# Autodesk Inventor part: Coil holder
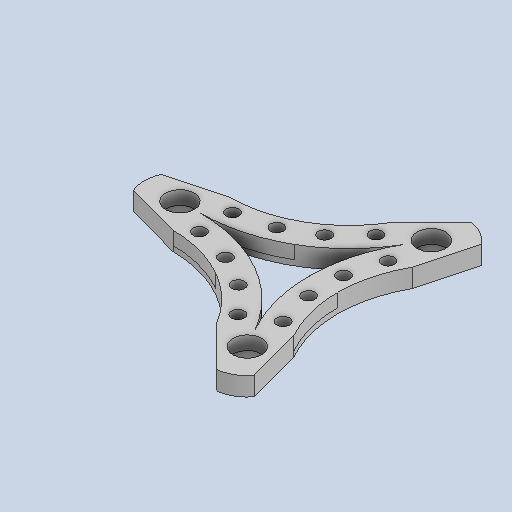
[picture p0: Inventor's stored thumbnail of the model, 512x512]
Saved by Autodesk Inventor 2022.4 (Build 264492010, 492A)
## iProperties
Created: 2023-09
Part Number: Coil holder
Material: Generic
Document SubType Name: Modeling
Designer: tmass
Density: 1 g/cm^3
Appearance: Default
Author: tmass
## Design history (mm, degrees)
derived "Fidget_bottom_3cm.ipt"
sketch "Sketch1"
  geometry: L1 (8.106, -10.67)-(-12.36, -5.175); L2 (-15.542, 0)-(79.177, 0); L3 (8.106, 10.67)-(-12.36, 5.175); L4 (65.181, -22.282)-(70.655, -42.754); L5 (46.699, -32.952)-(61.691, -47.929); L6 (46.699, 32.952)-(61.691, 47.929); L7 (65.181, 22.282)-(70.655, 42.754); A1 r 45.5 centre (7.567, -56.167) between (30.317, -16.763) and (8.106, -10.67) reference; A2 r 13.4 centre (0, 0) between (8.106, 10.67) and (8.106, -10.67) reference; A3 r 13.4 centre (59.993, -34.637) between (46.699, -32.952) and (65.181, -22.282) reference; A4 r 13.4 centre (59.993, 34.637) between (65.181, 22.282) and (46.699, 32.952) reference; A5 r 45.5 centre (7.567, 56.167) between (30.317, 16.763) and (46.699, 32.952) reference; A6 r 45.5 centre (7.567, 56.167) between (8.106, 10.67) and (30.317, 16.763) reference; A7 r 45.5 centre (7.567, -56.167) between (46.699, -32.952) and (30.317, -16.763) reference; A8 r 45.5 centre (104.852, 0) between (65.181, 22.282) and (59.352, 0) reference; A9 r 45.5 centre (104.852, 0) between (59.352, 0) and (65.181, -22.282) reference; 2 further points
  constraints: 14 end point, 1 horizontal, 1 point on circle, 1 symmetric about line, 19 other
  dimensions: "d3" = 360 deg dimension on point (39.995, 0) L1.start (derived)
extrude "Extrusion1" cut sketch "Sketch1" distance "d5" = 10; taper "d6" = 0 deg
feature "Solid4::Fidget_bottom_3cm.ipt" dims "d0" = 10
tag "TaggingFeature1"
body "Solid1"
